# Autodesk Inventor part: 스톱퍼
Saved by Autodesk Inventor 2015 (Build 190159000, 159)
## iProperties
Created: 2024-11
Part Number: 스톱퍼
Material: 일반
Document SubType Name: Modeling
Designer: 102-5
Density: 1 g/cm^3
Appearance: 기본값
Author: 102-5
Author: jhkim
Creation Date: 2024-10-25
Sending System: Autodesk Inventor 2025
Preprocessor: ST-DEVELOPER v20
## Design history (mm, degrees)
node "스톱퍼1"
node "솔리드1"
node "기준1"
